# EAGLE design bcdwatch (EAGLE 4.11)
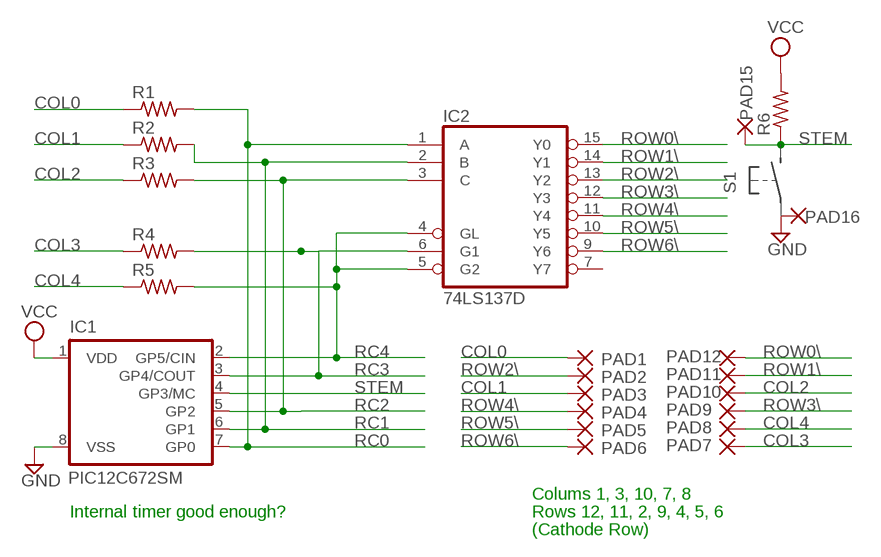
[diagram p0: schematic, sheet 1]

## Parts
IC1  PIC12C672SM  [SO-08M]
IC2  74LS137D  [SO16]
PAD1  SMD2  [SMD2]
PAD2  SMD2  [SMD2]
PAD3  SMD2  [SMD2]
PAD4  SMD2  [SMD2]
PAD5  SMD2  [SMD2]
PAD6  SMD2  [SMD2]
PAD7  SMD2  [SMD2]
PAD8  SMD2  [SMD2]
PAD9  SMD2  [SMD2]
PAD10  SMD2  [SMD2]
PAD11  SMD2  [SMD2]
PAD12  SMD2  [SMD2]
PAD15  SMD2  [SMD2]
PAD16  SMD2  [SMD2]
R1  R-US_R0805  [R0805]
R2  R-US_R0805  [R0805]
R3  R-US_R0805  [R0805]
R4  R-US_R0805  [R0805]
R5  R-US_R0805  [R0805]
R6  R-US_R0805  [R0805]

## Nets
COL0: PAD1.1(P) R1.1
COL1: PAD3.1(P) R2.1
COL2: PAD10.1(P) R3.1
COL3: PAD7.1(P) R4.1
COL4: PAD8.1(P) R5.1
GND: IC1.8(VSS) PAD16.1(P)
RC0: IC1.7(GP0) IC2.1(A) R1.2
RC1: IC1.6(GP1) IC2.2(B) R2.2
RC2: IC1.5(GP2) IC2.3(C) R3.2
RC3: IC1.3(GP4/COUT) IC2.6(G1) R4.2
RC4: IC1.2(GP5/CIN) IC2.4(GL) IC2.5(G2) R5.2
ROW0\: IC2.15(Y0) PAD12.1(P)
ROW1\: IC2.14(Y1) PAD11.1(P)
ROW2\: IC2.13(Y2) PAD2.1(P)
ROW3\: IC2.12(Y3) PAD9.1(P)
ROW4\: IC2.11(Y4) PAD4.1(P)
ROW5\: IC2.10(Y5) PAD5.1(P)
ROW6\: IC2.9(Y6) PAD6.1(P)
STEM: IC1.4(GP3/MC) PAD15.1(P) R6.1
VCC: IC1.1(VDD) R6.2
Unconnected: IC2.7(Y7)

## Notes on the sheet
- Colums 1, 3, 10, 7, 8
- Internal timer good enough? | Rows 12, 11, 2, 9, 4, 5, 6
- (Cathode Row)

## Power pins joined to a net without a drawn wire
GND: IC2.8(GND)
VCC: IC2.16(VCC)

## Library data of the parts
IC1 = microchip:PIC12C*?: MICROCONTROLLER
IC2 = 74xx-us:74*137: 3-line to 8-line DECODER/DEMULTIPLEXER, address LATCH
PAD1-PAD12 PAD15 PAD16 = wirepad:SMD2: SMD PAD
R1-R6 = rcl:R-US_: RESISTOR, American symbol

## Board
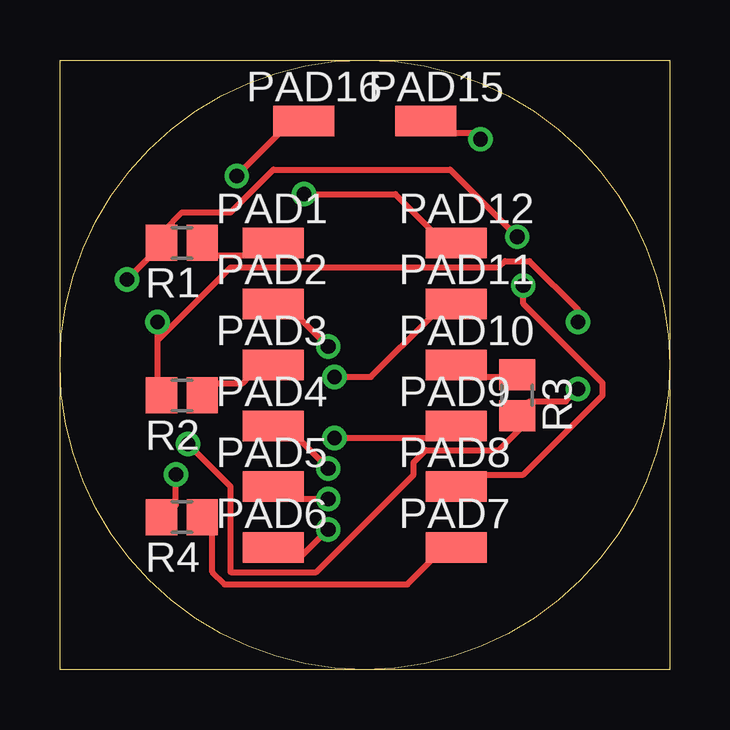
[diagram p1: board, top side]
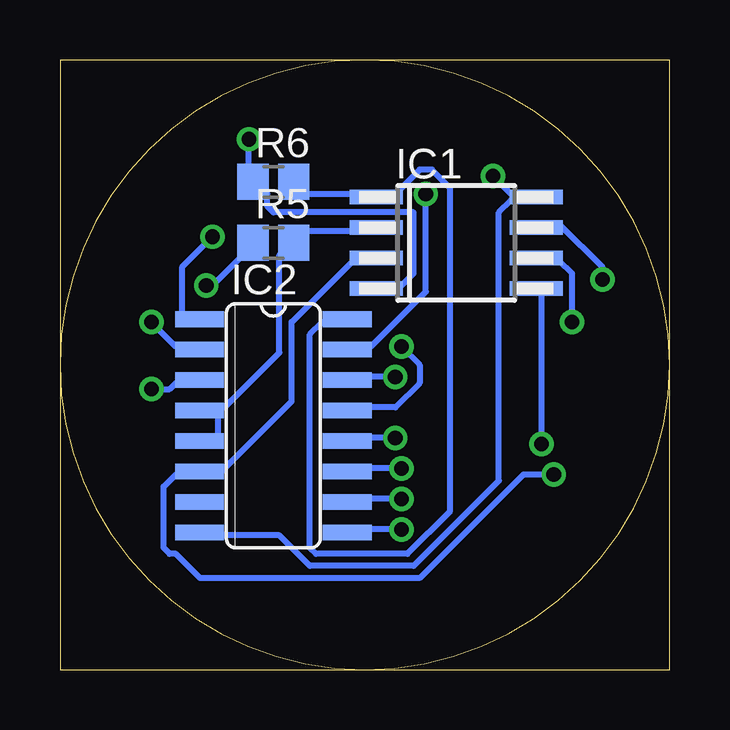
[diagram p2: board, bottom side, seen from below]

Size 25.4 x 25.4 mm. Coordinates in mm from the lower left corner, seen from the top.
Outline: 0,12.7 0,0 25.4,0 25.4,12.7
Outline: 0,12.7 0,25.4 24.13,25.4 25.4,25.4 25.4,12.7
Outline: 0,12.7 arc-180 25.4,12.7
Outline: 25.4,12.7 arc-180 0,12.7
Copper layers (1*16): Top 0.035mm / dielectric 1.5mm / Bottom 0.035mm
Design rules "default": minimum track width 10mil, minimum drill 24mil, track to track 8mil, track to pad 8mil, pad to pad 8mil, via to via 8mil, smd to smd 8mil, copper to edge 40mil, drill to drill 8mil, minimum pad ring 10mil, minimum via ring 8mil, stop-mask expansion 4mil, vias tented up to drill 0mil, thermal gap 10mil

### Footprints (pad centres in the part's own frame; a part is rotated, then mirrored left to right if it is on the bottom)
SO-08M = smd 0.6 x 2.2: 1 -1.905,-3.33; 2 -0.635,-3.33; 3 0.635,-3.33; 4 1.905,-3.33; 5 1.905,3.33; 6 0.635,3.33; 7 -0.635,3.33; 8 -1.905,3.33
SO16 = smd 0.66 x 2.032: 1 -4.445,-3.073; 2 -3.175,-3.073; 3 -1.905,-3.073; 4 -0.635,-3.073; 5 0.635,-3.073; 6 1.905,-3.073; 7 3.175,-3.073; 8 4.445,-3.073; 9 4.445,3.073; 10 3.175,3.073; 11 1.905,3.073; 12 0.635,3.073; 13 -0.635,3.073; 14 -1.905,3.073; 15 -3.175,3.073; 16 -4.445,3.073
SMD2 = smd 1.27 x 2.54: 1 0,0
R0805 = smd 1.3 x 1.5: 1 -0.85,0; 2 0.85,0

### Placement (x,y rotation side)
IC1  8.89,17.78 270 bottom
IC2  16.51,10.16 270 bottom
PAD1  8.89,17.78 270 top
PAD2  8.89,15.24 270 top
PAD3  8.89,12.7 270 top
PAD4  8.89,10.16 270 top
PAD5  8.89,7.62 270 top
PAD6  8.89,5.08 270 top
PAD7  16.51,5.08 270 top
PAD8  16.51,7.62 270 top
PAD9  16.51,10.16 270 top
PAD10  16.51,12.7 270 top
PAD11  16.51,15.24 270 top
PAD12  16.51,17.78 270 top
PAD15  15.24,22.86 270 top
PAD16  10.16,22.86 270 top
R1  5.08,17.78 180 top
R2  5.08,11.43 180 top
R3  19.05,11.43 270 top
R4  5.08,6.35 180 top
R5  16.51,17.78 0 bottom
R6  16.51,20.32 0 bottom

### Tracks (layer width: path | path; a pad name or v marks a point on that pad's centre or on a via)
COL0
  Top 0.254: R1.1 6.35,17.27 7.87,17.27 PAD1.1
COL1
  Top 0.254: R2.1 6.35,11.94 7.62,11.94 7.87,12.19 PAD3.1
COL2
  Top 0.254: R3.1 18.54,12.19 17.53,12.19 PAD10.1
COL3
  Top 0.254: R4.1 6.35,5.84 6.35,4.06 6.86,3.56 14.48,3.56 15.49,4.57 PAD7.1
COL4  (via drill 0.61)
  Top 0.254: v19.3,16 19.3,15.24 22.61,11.94 22.61,11.43 19.3,8.13 17.53,8.13 PAD8.1
  Bottom 0.254: v19.3,16 19.05,16 17.78,17.27 R5.1
GND  (via drill 0.61)
  Top 0.254: v7.37,20.57 9.14,22.35 PAD16.1
  Bottom 0.254: IC2.8 18.8,5.59 16.26,5.59 14.99,4.32 10.67,4.32 7.11,7.87 7.11,19.05 6.6,19.56 IC1.8 6.6,19.81 v7.37,20.57
RC0  (via drill 0.61)
  Top 0.254: v2.79,16.26 3.81,17.27 R1.2 4.32,18.29 5.08,19.05 7.11,19.05 8.89,20.83 16.26,20.83 v19.05,18.03
  Bottom 0.254: v2.79,16.26 2.79,16.76 4.57,18.54 IC1.7 | v19.05,18.03 20.32,16.76 20.32,14.73 IC2.1
RC1  (via drill 0.61)
  Top 0.254: 4.06,13.72 v4.06,14.48 | 4.06,13.72 4.06,11.94 R2.2 | v21.59,14.48 21.59,14.99 19.56,17.02 18.54,17.02 18.29,16.76 7.11,16.76 4.06,13.72
  Bottom 0.254: v4.06,14.48 4.06,16.51 4.57,17.02 IC1.6 | v21.59,14.48 20.57,13.46 IC2.2
RC2  (via drill 0.61)
  Top 0.254: v21.59,11.68 21.08,11.18 19.56,11.18 R3.2 19.3,10.16 18.29,9.14 15.24,9.14 14.73,8.64 14.73,8.13 10.67,4.06 7.11,4.06 7.11,7.62 v5.33,9.4
  Bottom 0.254: v21.59,11.68 20.83,11.68 20.57,11.94 IC2.3 | v5.33,9.4 5.33,15.75 IC1.5
RC3  (via drill 0.61)
  Top 0.254: v4.83,8.13 4.83,6.86 R4.2
  Bottom 0.254: v4.83,8.13 6.1,8.13 10.41,3.81 19.56,3.81 20.57,4.83 20.83,4.83 21.08,5.08 21.08,7.62 20.57,8.13 IC2.6 18.8,8.13 15.75,11.18 15.75,14.48 13.21,17.02 IC1.3
RC4
  Bottom 0.254: IC2.5 18.8,9.65 18.8,10.67 IC2.4 18.8,10.92 18.54,10.92 16.26,13.21 16.26,17.27 R5.2 15.24,18.29 13.21,18.29 IC1.2
ROW0\  (via drill 0.61)
  Top 0.254: v10.16,19.81 13.97,19.81 15.49,18.29 PAD12.1
  Bottom 0.254: v10.16,19.81 10.16,15.75 12.45,13.46 IC2.15
ROW1\  (via drill 0.61)
  Top 0.254: v11.43,12.19 12.95,12.19 15.49,14.73 PAD11.1
  Bottom 0.254: v11.43,12.19 12.45,12.19 IC2.14
ROW2\  (via drill 0.61)
  Top 0.254: v11.18,13.46 9.91,14.73 PAD2.1
  Bottom 0.254: v11.18,13.46 10.41,12.7 10.41,11.94 11.43,10.92 12.45,10.92 IC2.13
ROW3\  (via drill 0.61)
  Top 0.254: v11.43,9.65 15.49,9.65 PAD9.1
  Bottom 0.254: v11.43,9.65 12.45,9.65 IC2.12
ROW4\  (via drill 0.61)
  Top 0.254: v11.18,8.38 9.91,9.65 PAD4.1
  Bottom 0.254: v11.18,8.38 12.45,8.38 IC2.11
ROW5\  (via drill 0.61)
  Top 0.254: v11.18,7.11 9.91,7.11 PAD5.1
  Bottom 0.254: v11.18,7.11 12.45,7.11 IC2.10
ROW6\  (via drill 0.61)
  Top 0.254: v11.18,5.84 9.91,4.57 PAD6.1
  Bottom 0.254: v11.18,5.84 12.45,5.84 IC2.9
STEM  (via drill 0.61)
  Top 0.254: v17.53,22.1 17.27,22.35 16.26,22.35 PAD15.1
  Bottom 0.254: IC1.4 11.18,16 10.67,16.51 10.67,19.05 16.51,19.05 16.76,19.3 16.76,19.81 R6.1 17.53,20.83 v17.53,22.1
VCC
  Bottom 0.254: R6.2 15.24,19.81 13.21,19.81 IC1.1 11.43,19.81 10.41,20.83 9.91,20.83 9.14,20.07 9.14,6.6 10.92,4.83 14.73,4.83 14.99,5.08 14.99,13.97 14.48,14.48 14.22,14.48 IC2.16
